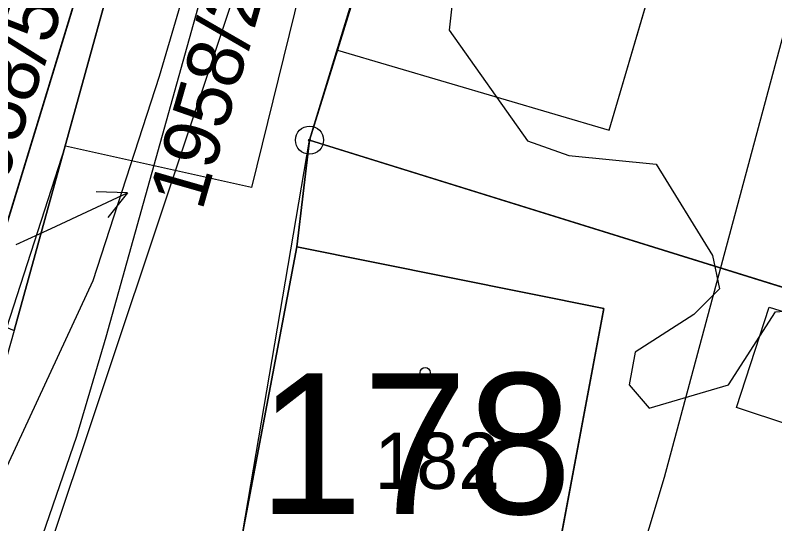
# Model space of a CAD drawing. Extents: x -706130 to -698555, y -971544 to -967260.
# Drawn here: x -704338.67 to -704311.66, y -970211.32 to -970193.24 of the extents above; entities that cross this region are included whole.
import ezdxf

# ---------------------------------------------------------------- set-up
doc = ezdxf.new("R2010")
doc.units = 0
for name, color, linetype in [('_Doplněk budov pro zastavěnost', 7, 'Continuous'), ('BPEJ I-II trida ochrany S', 7, 'Continuous'), ('Docházková izochrona - BUS S', 7, 'Continuous'), ('Docházková izochrona - VLAK N', 7, 'Continuous'), ('Kanalizace_stoka bez rozlišení N', 7, 'Continuous'), ('KN_Budovy', 7, 'Continuous'), ('KN_Budovy_cisla_domovni', 7, 'Continuous'), ('KN_Hranice_parcel', 7, 'Continuous'), ('KN_Hranice_parcel_vnitrni_kresba', 7, 'Continuous'), ('KN_Parcelni cisla', 7, 'Continuous'), ('KN_Parcelni cisla_sipky', 7, 'Continuous'), ('KN_Polygon parcely', 7, 'Continuous'), ('KN_POZEMKY_13_ZASTAVENA PLOCHA', 7, 'Continuous'), ('KN_POZEMKY_14_OSTATNI PLOCHA', 7, 'Continuous'), ('KN_POZEMKY_7_TTP', 7, 'Continuous'), ('KN_VYUZITI_16_ostatni plocha_silnice', 7, 'Continuous'), ('KN_Značky bodu BP', 7, 'Continuous'), ('KN_Značky budov', 7, 'Continuous'), ('Komunikace III třídy osy S', 7, 'Continuous'), ('Plochy doprava silniční - silnice III třídy S', 7, 'Continuous'), ('Plochy smíšené obytné venkovské S', 7, 'Continuous'), ('Plochy vodní a vodních toku_linie zatrubněný tok S', 7, 'Continuous'), ('Plynovody STL S', 7, 'Continuous'), ('Regulační bloky zastavěné S', 7, 'Continuous'), ('Trasy cykloturistické N', 7, 'Continuous'), ('Vodovodní řady - rozváděcí S', 7, 'Continuous'), ('Záplavové území stanovene S', 7, 'Continuous')]:
    doc.layers.add(name, color=color, linetype=linetype)

msp = doc.modelspace()

# ---------------------------------------------------------------- linework, layer by layer
at = {"layer": '_Doplněk budov pro zastavěnost'}
msp.add_lwpolyline([(-704311.85, -970203.62), (-704304.14, -970206.02), (-704305.4, -970209.71), (-704313.02, -970207.18)], close=True, dxfattribs=at)
at = {"layer": 'BPEJ I-II trida ochrany S'}
msp.add_line((-704338.7, -970204.45), (-704332.12, -970180.63), dxfattribs=at)
at = {"layer": 'Docházková izochrona - BUS S'}
msp.add_arc((-704361.829, -969946.93), 400, 155.51821, 17.33949, dxfattribs=at)
at = {"layer": 'Docházková izochrona - VLAK N'}
msp.add_circle((-704165.451, -969778.767), 800, dxfattribs=at)
at = {"layer": 'Kanalizace_stoka bez rozlišení N'}
msp.add_lwpolyline([(-704315.708, -970108.899), (-704316.113, -970109.917), (-704324.867, -970134.026), (-704326.632, -970179.784), (-704337.75, -970213.085), (-704365.425, -970272.107), (-704371.374, -970294.506), (-704373.709, -970351.804), (-704376.113, -970385.719), (-704398.194, -970423.758)], dxfattribs=at)
at = {"layer": 'KN_Budovy'}
for points in [[(-704327.21, -970194.48), (-704317.55, -970197.33), (-704312.52, -970180.25), (-704322.1, -970177.43), (-704324.27, -970184.8), (-704325.58, -970189.23)], [(-704330.57, -970211.6), (-704325.19, -970212.62), (-704325.4, -970213.75), (-704322.55, -970214.29), (-704322.36, -970213.26), (-704319.63, -970213.77), (-704317.74, -970203.66), (-704328.65, -970201.47)]]:
    msp.add_lwpolyline(points, close=True, dxfattribs=at)
at = {"layer": 'KN_Hranice_parcel'}
for p, q in [((-704338.7, -970204.45), (-704332.12, -970180.63)), ((-704336.36, -970192.11), (-704339.97, -970203.93)), ((-704303.37, -970205.4), (-704328.2, -970197.68))]:
    msp.add_line(p, q, dxfattribs=at)
for points in [[(-704324.27, -970184.8), (-704325.58, -970189.23), (-704327.21, -970194.48), (-704328.2, -970197.68)], [(-704328.2, -970197.68), (-704328.65, -970201.47), (-704330.57, -970211.6), (-704331.07, -970212.4)]]:
    msp.add_lwpolyline(points, dxfattribs=at)
at = {"layer": 'KN_Hranice_parcel_vnitrni_kresba'}
for p, q in [((-704317.55, -970197.33), (-704312.52, -970180.25)), ((-704327.21, -970194.48), (-704317.55, -970197.33)), ((-704328.65, -970201.47), (-704317.74, -970203.66)), ((-704317.74, -970203.66), (-704319.63, -970213.77))]:
    msp.add_line(p, q, dxfattribs=at)
at = {"layer": 'KN_Parcelni cisla_sipky'}
for p, q in [((-704337.39, -970200.82), (-704334.67, -970199.552)), ((-704334.67, -970199.552), (-704335.789, -970199.521)), ((-704334.67, -970199.552), (-704335.366, -970200.429)), ((-704338.63, -970201.39), (-704337.39, -970200.82))]:
    msp.add_line(p, q, dxfattribs=at)
at = {"layer": 'KN_Polygon parcely'}
for points in [[(-704316.23, -970174.92), (-704322.1, -970177.43), (-704324.27, -970184.8), (-704325.58, -970189.23), (-704327.21, -970194.48), (-704328.2, -970197.68), (-704303.37, -970205.4), (-704298.28, -970181.17), (-704297.85, -970179.64), (-704298.79, -970179.28), (-704299.67, -970181.58)], [(-704336.36, -970192.11), (-704339.97, -970203.93), (-704338.7, -970204.45), (-704332.12, -970180.63)], [(-704343.55, -970202.46), (-704339.97, -970203.93), (-704336.36, -970192.11), (-704342.04, -970190.55)], [(-704330.57, -970211.6), (-704331.07, -970212.4), (-704327.96, -970220.42), (-704323.42, -970223.6), (-704319.16, -970226.59), (-704310.29, -970235.93), (-704306.81, -970220.57), (-704303.37, -970205.4), (-704328.2, -970197.68), (-704328.65, -970201.47)]]:
    msp.add_lwpolyline(points, close=True, dxfattribs=at)
for points in [[(-704332.12, -970180.63), (-704338.7, -970204.45), (-704340.61, -970211.17), (-704352.93, -970235.65), (-704356.76, -970243.29), (-704364.41, -970258.54), (-704369.07, -970266.34), (-704369.54, -970267.12), (-704375.45, -970281.66), (-704375.62, -970282.06), (-704376.41, -970288.62)], [(-704366.65, -970284.79), (-704361.08, -970269.38), (-704350.46, -970248.43), (-704337.45, -970223.6), (-704331.07, -970212.4), (-704330.57, -970211.6), (-704328.65, -970201.47), (-704328.2, -970197.68), (-704327.21, -970194.48), (-704325.58, -970189.23)]]:
    msp.add_lwpolyline(points, dxfattribs=at)
at = {"layer": 'KN_POZEMKY_13_ZASTAVENA PLOCHA'}
for p, q in [((-704327.21, -970194.48), (-704325.58, -970189.23)), ((-704328.2, -970197.68), (-704327.21, -970194.48)), ((-704328.65, -970201.47), (-704328.2, -970197.68)), ((-704303.37, -970205.4), (-704328.2, -970197.68)), ((-704328.2, -970197.68), (-704303.37, -970205.4)), ((-704330.57, -970211.6), (-704328.65, -970201.47))]:
    msp.add_line(p, q, dxfattribs=at)
at = {"layer": 'KN_POZEMKY_14_OSTATNI PLOCHA'}
for p, q in [((-704338.7, -970204.45), (-704332.12, -970180.63)), ((-704325.58, -970189.23), (-704327.21, -970194.48)), ((-704327.21, -970194.48), (-704328.2, -970197.68)), ((-704328.2, -970197.68), (-704328.65, -970201.47)), ((-704328.65, -970201.47), (-704330.57, -970211.6))]:
    msp.add_line(p, q, dxfattribs=at)
at = {"layer": 'KN_POZEMKY_7_TTP'}
for p, q in [((-704332.12, -970180.63), (-704338.7, -970204.45)), ((-704336.36, -970192.11), (-704339.97, -970203.93)), ((-704339.97, -970203.93), (-704336.36, -970192.11))]:
    msp.add_line(p, q, dxfattribs=at)
at = {"layer": 'KN_VYUZITI_16_ostatni plocha_silnice'}
for p, q in [((-704338.7, -970204.45), (-704332.12, -970180.63)), ((-704325.58, -970189.23), (-704327.21, -970194.48)), ((-704327.21, -970194.48), (-704328.2, -970197.68)), ((-704328.2, -970197.68), (-704328.65, -970201.47)), ((-704328.65, -970201.47), (-704330.57, -970211.6))]:
    msp.add_line(p, q, dxfattribs=at)
at = {"layer": 'KN_Značky bodu BP'}
for radius in [0.5, 0.0303]:
    msp.add_circle((-704328.2, -970197.68), radius, dxfattribs=at)
at = {"layer": 'KN_Značky budov'}
msp.add_circle((-704324.087, -970205.939), 0.175, dxfattribs=at)
at = {"layer": 'Komunikace III třídy osy S'}
msp.add_lwpolyline([(-704330.93, -970188.51), (-704335.437, -970204.681), (-704336.48, -970208.22), (-704338.18, -970213.14), (-704340.791, -970218.395), (-704362.238, -970261.156), (-704368.668, -970276.027), (-704371.631, -970286.925), (-704374.154, -970304.881), (-704375.815, -970349.829), (-704377.52, -970379.09), (-704378.33, -970382.9), (-704379.81, -970387.16), (-704381.8, -970391.97), (-704383.72, -970396.25), (-704386.32, -970401.18), (-704392.36, -970410.73), (-704399.98, -970422.96)], dxfattribs=at)
at = {"layer": 'Plochy doprava silniční - silnice III třídy S'}
for p, q in [((-704332.12, -970180.63), (-704338.7, -970204.45)), ((-704327.21, -970194.48), (-704325.58, -970189.23)), ((-704328.2, -970197.68), (-704327.21, -970194.48)), ((-704328.65, -970201.47), (-704328.2, -970197.68)), ((-704330.57, -970211.6), (-704328.65, -970201.47))]:
    msp.add_line(p, q, dxfattribs=at)
at = {"layer": 'Plochy smíšené obytné venkovské S'}
for p, q in [((-704338.7, -970204.45), (-704332.12, -970180.63)), ((-704325.58, -970189.23), (-704327.21, -970194.48)), ((-704327.21, -970194.48), (-704328.2, -970197.68)), ((-704328.2, -970197.68), (-704328.65, -970201.47)), ((-704328.65, -970201.47), (-704330.57, -970211.6))]:
    msp.add_line(p, q, dxfattribs=at)
at = {"layer": 'Plochy vodní a vodních toku_linie zatrubněný tok S'}
msp.add_lwpolyline([(-704322.195, -970231.658), (-704315.577, -970209.662), (-704310.452, -970190.609), (-704310.025, -970177.978), (-704308.103, -970157.425), (-704307.462, -970138.586), (-704307.462, -970124.666), (-704314.585, -970112.421), (-704319.309, -970105.942)], dxfattribs=at)
at = {"layer": 'Plynovody STL S'}
msp.add_lwpolyline([(-704375.535, -970290.001), (-704372.96, -970278.67), (-704368.945, -970266.662), (-704368.62, -970265.69), (-704365.144, -970258.522), (-704361.06, -970250.1), (-704360.06, -970248.15), (-704357.178, -970242.53), (-704352.1, -970232.63), (-704348.876, -970226.302), (-704343.43, -970215.61), (-704341.145, -970210.248), (-704340.08, -970207.75), (-704336.877, -970197.883), (-704330.259, -970199.357), (-704330.25, -970199.36), (-704327.768, -970189.289)], dxfattribs=at)
at = {"layer": 'Regulační bloky zastavěné S'}
for p, q in [((-704338.7, -970204.45), (-704332.12, -970180.63)), ((-704332.12, -970180.63), (-704338.7, -970204.45)), ((-704327.21, -970194.48), (-704325.58, -970189.23)), ((-704325.58, -970189.23), (-704327.21, -970194.48)), ((-704328.2, -970197.68), (-704327.21, -970194.48)), ((-704327.21, -970194.48), (-704328.2, -970197.68)), ((-704328.65, -970201.47), (-704328.2, -970197.68)), ((-704328.2, -970197.68), (-704328.65, -970201.47)), ((-704330.57, -970211.6), (-704328.65, -970201.47)), ((-704328.65, -970201.47), (-704330.57, -970211.6))]:
    msp.add_line(p, q, dxfattribs=at)
at = {"layer": 'Trasy cykloturistické N'}
msp.add_lwpolyline([(-704397.28, -970427.29), (-704386.46, -970409.76), (-704381.94, -970403.15), (-704375.12, -970393.19), (-704372.65, -970386.41), (-704370.59, -970346.53), (-704369.52, -970316.88), (-704368.75, -970300.09), (-704366.65, -970284.79), (-704361.08, -970269.38), (-704350.46, -970248.43), (-704337.45, -970223.6), (-704330.57, -970211.6), (-704328.2, -970197.68), (-704324.27, -970184.8)], dxfattribs=at)
at = {"layer": 'Vodovodní řady - rozváděcí S'}
msp.add_lwpolyline([(-704328.67, -970167.56), (-704328.75, -970173.78), (-704329.18, -970178.73), (-704330.11, -970183.73), (-704333.54, -970195.42), (-704335.9, -970202.68), (-704339.12, -970209.61), (-704341.09, -970213.98)], dxfattribs=at)
at = {"layer": 'Záplavové území stanovene S'}
msp.add_lwpolyline([(-704323.078, -970192.375), (-704323.23, -970193.77), (-704320.453, -970197.703), (-704318.979, -970198.229), (-704315.875, -970198.531), (-704313.875, -970201.781), (-704313.625, -970202.969), (-704314.531, -970203.875), (-704316.625, -970205.219), (-704316.828, -970206.375), (-704316.125, -970207.203), (-704313.297, -970206.375), (-704311.625, -970203.781), (-704309.817, -970203.637), (-704305.375, -970205.281), (-704302.625, -970204.703), (-704301.336, -970202.914), (-704299.923, -970199.125), (-704296.823, -970197.375), (-704294.823, -970190.875)], dxfattribs=at)

# ---------------------------------------------------------------- texts
at = {"layer": 'KN_Budovy_cisla_domovni'}
msp.add_text('178', height=5, dxfattribs=at).set_placement((-704330.022, -970210.969))
at = {"layer": 'KN_Parcelni cisla'}
for s, rotation, p in [('1958/22', 74, (-704332.02, -970200.231)), ('1958/58', 72, (-704339.475, -970200.695))]:
    msp.add_text(s, height=2, rotation=rotation, dxfattribs=at).set_placement(p)
msp.add_text('182', height=2, dxfattribs=at).set_placement((-704325.89, -970210.08))

doc.saveas('drawing.dxf')
